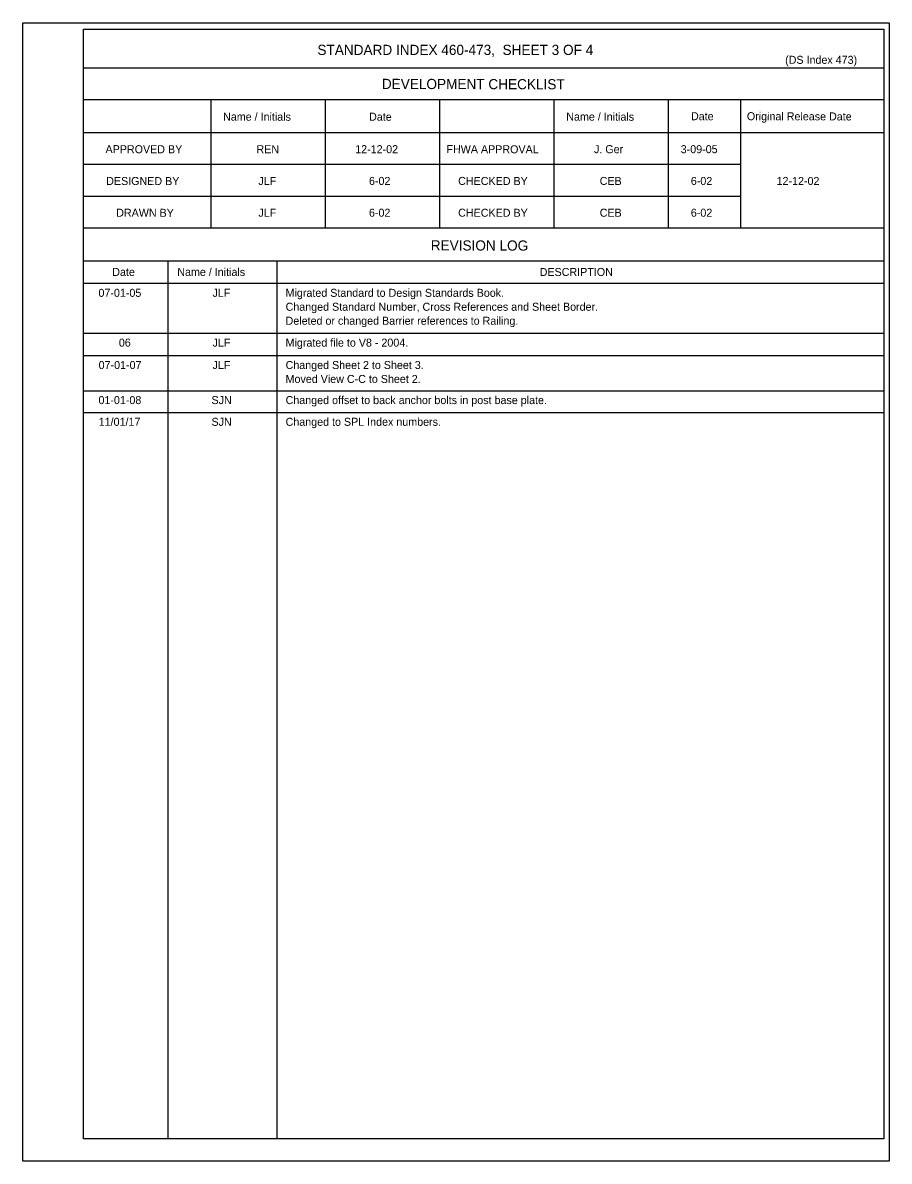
# Model space of a CAD drawing. Extents: x 21526.6 to 21595.9, y 56117 to 56157.3.
# Drawn here: x 21574.14 to 21595.95, y 56124.78 to 56153.45 of the extents above; entities that cross this region are included whole.
import ezdxf

# ---------------------------------------------------------------- set-up
doc = ezdxf.new("R2010")
doc.units = 0
doc.layers.add('Border', color=7, linetype='Continuous')
doc.layers.add('PlotBorder_dp', color=7, linetype='Continuous')

msp = doc.modelspace()

# ---------------------------------------------------------------- linework, layer by layer
at = {"layer": 'Border'}
for p, q in [((21595.814, 56152.307), (21575.667, 56152.307)), ((21595.814, 56151.507), (21575.667, 56151.507)), ((21578.867, 56151.507), (21578.867, 56148.279)), ((21581.747, 56151.507), (21581.747, 56148.279)), ((21584.627, 56151.507), (21584.627, 56148.279)), ((21587.507, 56151.507), (21587.507, 56148.279)), ((21590.387, 56151.507), (21590.387, 56148.279)), ((21592.202, 56151.507), (21592.202, 56148.279)), ((21595.814, 56150.679), (21575.667, 56150.679)), ((21592.202, 56149.879), (21575.667, 56149.879)), ((21592.202, 56149.079), (21575.667, 56149.079)), ((21595.814, 56148.279), (21575.667, 56148.279)), ((21595.814, 56147.451), (21575.667, 56147.451)), ((21577.787, 56147.451), (21577.787, 56125.345)), ((21580.529, 56147.451), (21580.529, 56125.345)), ((21595.814, 56146.887), (21575.667, 56146.887))]:
    msp.add_line(p, q, dxfattribs=at)
msp.add_lwpolyline([(21575.667, 56153.287), (21595.814, 56153.287), (21595.814, 56125.345), (21575.667, 56125.345)], close=True, dxfattribs=at)
at = {"layer": 'PlotBorder_dp'}
for p, q in [((21575.667, 56145.633), (21595.814, 56145.633)), ((21575.667, 56145.069), (21595.814, 56145.069)), ((21575.667, 56144.186), (21595.814, 56144.186)), ((21575.667, 56143.639), (21595.814, 56143.639)), ((21574.136, 56124.783), (21574.136, 56124.783))]:
    msp.add_line(p, q, dxfattribs=at)
msp.add_lwpolyline([(21574.136, 56153.45), (21595.95, 56153.45), (21595.95, 56124.783), (21574.136, 56124.783)], close=True, dxfattribs=at)

# ---------------------------------------------------------------- texts
at = {"layer": 'Border'}
for s, height, p in [('STANDARD INDEX 460-473,  SHEET 3 OF 4', 0.256, (21581.554, 56152.639)), ('(DS Index 473)', 0.2016, (21593.329, 56152.416)), ('REN', 0.2016, (21580.019, 56150.166)), ('12-12-02', 0.2016, (21582.506, 56150.166)), ('J. Ger', 0.2016, (21588.517, 56150.166)), ('3-09-05', 0.2016, (21590.7, 56150.166)), ('JLF', 0.2016, (21580.067, 56149.366)), ('6-02', 0.2016, (21582.852, 56149.366)), ('CEB', 0.2016, (21588.661, 56149.366)), ('6-02', 0.2016, (21590.955, 56149.366)), ('12-12-02', 0.2016, (21593.114, 56149.366)), ('JLF', 0.2016, (21580.067, 56148.566)), ('6-02', 0.2016, (21582.852, 56148.566)), ('CEB', 0.2016, (21588.661, 56148.566)), ('6-02', 0.2016, (21590.955, 56148.566)), ('DESCRIPTION', 0.2016, (21587.15, 56147.074)), ('07-01-05', 0.2016, (21576.042, 56146.549)), ('JLF', 0.2016, (21578.913, 56146.549)), ('Migrated Standard to Design Standards Book.', 0.2016, (21580.753, 56146.549)), ('Changed Standard Number, Cross References and Sheet Border.', 0.2016, (21580.753, 56146.198)), ('Deleted or changed Barrier references to Railing.', 0.2016, (21580.753, 56145.846)), ('06', 0.2016, (21576.555, 56145.295)), ('JLF', 0.2016, (21578.914, 56145.295)), ('Migrated file to V8 - 2004.', 0.2016, (21580.753, 56145.295)), ('07-01-07', 0.2016, (21576.046, 56144.731)), ('JLF', 0.2016, (21578.914, 56144.731)), ('Changed Sheet 2 to Sheet 3.', 0.2016, (21580.753, 56144.731)), ('Moved View C-C to Sheet 2.', 0.2016, (21580.753, 56144.38)), ('01-01-08', 0.2016, (21576.042, 56143.848)), ('SJN', 0.2016, (21578.888, 56143.848)), ('Changed offset to back anchor bolts in post base plate.', 0.2016, (21580.753, 56143.848)), ('11/01/17', 0.2016, (21576.048, 56143.301)), ('SJN', 0.2016, (21578.888, 56143.301)), ('Changed to SPL Index numbers.', 0.2016, (21580.753, 56143.301))]:
    msp.add_text(s, height=height, dxfattribs=at).set_placement(p)
for s, height, p in [('DEVELOPMENT CHECKLIST', 0.256, (21583.176, 56151.783)), ('Name / Initials', 0.2016, (21579.179, 56150.986)), ('Date', 0.2016, (21582.854, 56150.984)), ('Name / Initials', 0.2016, (21587.819, 56150.986)), ('Date', 0.2016, (21590.959, 56150.996)), ('Original Release Date', 0.2016, (21592.366, 56150.996)), ('APPROVED BY', 0.2016, (21576.219, 56150.167)), ('FHWA APPROVAL', 0.2016, (21584.802, 56150.167)), ('DESIGNED BY', 0.2016, (21576.236, 56149.366)), ('CHECKED BY', 0.2016, (21585.097, 56149.367)), ('DRAWN BY', 0.2016, (21576.488, 56148.566)), ('CHECKED BY', 0.2016, (21585.097, 56148.567)), ('REVISION LOG', 0.256, (21584.407, 56147.717)), ('Name / Initials', 0.2016, (21578.026, 56147.076)), ('Date', 0.2016, (21576.389, 56147.075))]:
    msp.add_text(s, height=height, rotation=359.8756, dxfattribs=at).set_placement(p)

doc.saveas('drawing.dxf')
